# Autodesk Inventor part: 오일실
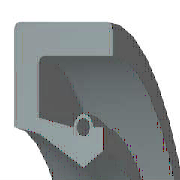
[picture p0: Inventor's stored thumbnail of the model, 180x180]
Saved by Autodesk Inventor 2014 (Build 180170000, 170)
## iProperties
IsCustomPart: 0
Created: 2009-02
Part Number: 오일실
Material: 고무
Description: 오일-실
Document SubType Name: Modeling
Standard: KS B 2804
Designer: 한국산업디자인학원 [http://gmhk.co.kr]
Standards Organization: KS
Language: ko-KR
Size Designation: S - 17 30 8
Categories: <MemberInstance><Categories><Category DisplayName="샤프트 부품" InternalName="7f7aeb1f-a693-4053-b835-cee3144e0d98" Mnemonic="SHFT"><Category DisplayName="실링" Intern
Density: 0.93 g/cm^3
Appearance: 고무 - 검은색 - 버전 1.1
Author: pww
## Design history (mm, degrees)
revolve "본체" stored, may be unused: angle "d17" = 90 deg
revolve "스프링1" stored, may be unused: angle "d18" = 90 deg
body "Solid1"
sketch "스케치1"
  geometry: L1 (0, 15)-(8, 15); L2 (8, 15)-(8, 13.75); L3 (8, 13.75)-(1.75, 13.75); L4 (0, 15)-(0, 10.6); L5 (0, 10.6)-(1.75, 10.25); L6 (1.75, 10.25)-(4.9, 8.5); L7 (4.9, 8.5)-(0, 8.5); L8 (6.3, 9.375)-(6.3, 10.6); L9 (0, 0)-(9.586, 0) reference; L10 (4.9, 8.5)-(6.3, 9.375); L11 (0, 18)-(0, -3) reference; L12 (-1.917, 0)-(11.503, 0) reference; L13 (4.2, 10.6)-(1.75, 11.09); L14 (1.75, 11.09)-(1.75, 13.75); L15 (6.3, 10.6)-(5.6, 10.6); C1 r 0.455 at (4.9, 10.6); A1 r 0.7 centre (4.9, 10.6) between (5.6, 10.6) and (4.2, 10.6)
  constraints: 26 end point, 5 horizontal alignment, 4 perpendicular, 2 centre point, 2 collinear, 2 horizontal, 2 parallel, 2 point on circle, 2 point on line, 2 vertical alignment, 1 coincident
  dimensions: "d0" = 30 diameter of L1 L9 (= SD2); "d1" = 18.75 diameter of L8.start L9 (= ABDM); "d2" = 1.25 distance of L1.end L2.end (computed from SD); "d3" = 0.91 diameter of C1 (= SPDI); "d4" = 1.4 diameter of A1 (= SPDA); "d5" = 17 diameter of L6.end L9 (= NND); "d6" = 20.5 diameter of L5.end L9 (= TKDM); "d7" = 21.2 diameter of L4.end L9 (= HLDM); "d8" = 4.9 distance from line of C1.centre L4 (= SPDST); "d9" = 6.3 distance between parallel lines of L8 L4 (= SDI); "d10" = 8 distance between parallel lines of L2 L4 (= SWDT); "d12" = 1.75 distance between parallel lines of L14 L4 (= SD)
fillet "모깎기1" dims "d11" = 0.3 (= RR)
other parameters: "SD2" = 30 [user parameter; used in 1 equation term], "SWDT" = 8 [user parameter; used in 1 equation term], "RR" = 0.3 [user parameter; used in 1 equation term], "SD" = 1.75 [user parameter; used in 2 equation terms], "NND" = 17 [user parameter; used in 1 equation term], "SPDA" = 1.4 [user parameter; used in 1 equation term], "SPDI" = 0.91 [user parameter; used in 1 equation term], "TKDM" = 20.5 [user parameter; used in 1 equation term], "HLDM" = 21.2 [user parameter; used in 1 equation term], "ABDM" = 18.75 [user parameter; used in 1 equation term], "SDI" = 6.3 [user parameter; used in 1 equation term], "SPDST" = 4.9 [user parameter; used in 1 equation term], "d13" = 0, "d14" = 0, "d15" = 0, "LAB" = 0.35 [user parameter]
